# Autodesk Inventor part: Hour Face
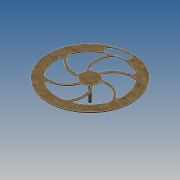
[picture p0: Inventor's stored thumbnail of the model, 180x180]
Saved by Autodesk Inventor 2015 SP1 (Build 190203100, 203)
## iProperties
Created: 2015-01
Part Number: Hour Face
Material: Generic
Document SubType Name: Modeling
Designer: Steve Brooks
Density: 1 g/cm^3
Appearance: IDS MDF
Author: Steve Brooks
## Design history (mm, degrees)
sketch "Sketch1"
  geometry: C1 r 3 at (-234.295, -144.93) reference; C2 r 6.747 at (-234.295, -144.93) reference; 1 further point
extrude "Extrusion1" new body sketch "Sketch1" distance "d0" = 108; taper "d1" = 0 deg
sketch "Sketch2"
  geometry: L1 (200.947, -79.304)-(203.637, -72.118) reference; C1 r 6.747 at (0, 0) reference; C2 r 3 at (0, 0) reference; C3 r 225 at (0, 0); 1 further point
  constraints: 1 centre point, 1 coincident
  dimensions: "d9" = 450 diameter of C3
extrude "Extrusion2" new body sketch "Sketch2" distance "d3" = 6; taper "d4" = 0 deg
sketch "Sketch3"
  geometry: L1 (0, 0)-(0, 198); L2 (0, 0)-(-77.365, 182.26); C1 r 3 at (0, 0) reference; C2 r 6.747 at (0, 0) reference; A1 r 20 centre (0, 198) between (0, 178) and (0, 218); A2 r 20 centre (-77.365, 182.26) between (-85.179, 200.67) and (-69.55, 163.85); A3 r 178 centre (0, 0) between (0, 178) and (-69.55, 163.85); A4 r 218 centre (0, 0) between (0, 218) and (-85.179, 200.67); 1 further point
  constraints: 8 point on circle, 4 centre point, 4 end point, 3 tangent, 2 coincident, 1 vertical
  dimensions: "d5" = 40 diameter of A1; "d6" = 198 distance of L1.end point (0, 0); "d21" = 40 diameter of A2; "d22" = 23 deg angle of L1 L2
sketch "Sketch4"
  geometry: C1 r 6.747 at (0, 0) reference; C2 r 3 at (0, 0) reference; A1 r 106.588 centre (45, 100.374) between (-36.681, 168.853) and (-41.383, 37.931); A2 r 116.588 centre (45, 100.374) between (-62.871, 144.608) and (-44.081, 25.158); A3 r 106.588 centre (-64.427, 89.158) between (-164.571, 52.66) and (-53.541, -16.873); A4 r 116.588 centre (-64.427, 89.158) between (-156.67, 17.856) and (-43.828, -25.596); A5 r 106.588 centre (-109.427, -11.216) between (-127.89, -116.193) and (-12.158, -54.804); A6 r 116.588 centre (-109.427, -11.216) between (-93.798, -126.752) and (0.253, -50.754); A7 r 106.588 centre (-45, -100.374) between (36.681, -168.853) and (41.383, -37.931); A8 r 116.588 centre (-45, -100.374) between (62.871, -144.608) and (44.081, -25.158); A9 r 106.588 centre (64.427, -89.158) between (164.571, -52.66) and (53.541, 16.873); A10 r 116.588 centre (64.427, -89.158) between (156.67, -17.856) and (43.828, 25.596); A11 r 106.588 centre (109.427, 11.216) between (131.472, 115.5) and (12.158, 54.804); A12 r 116.588 centre (109.427, 11.216) between (93.798, 126.752) and (-0.253, 50.754); A13 r 175 centre (0, 0) between (-76.495, 157.396) and (-164.581, 59.483); A14 r 175 centre (0, 0) between (98.062, 144.945) and (-30.776, 172.272); A15 r 175 centre (0, 0) between (174.556, -12.451) and (131.472, 115.5); A16 r 175 centre (0, 0) between (76.495, -157.396) and (164.581, -59.483); A17 r 175 centre (0, 0) between (-174.556, 12.451) and (-133.804, -112.789); A18 r 175 centre (0, 0) between (-98.062, -144.945) and (30.776, -172.272); A19 r 45 centre (0, 0) between (-42.317, 15.305) and (-44.642, -5.666); A20 r 45 centre (0, 0) between (42.317, -15.305) and (44.642, 5.666); A21 r 45 centre (0, 0) between (-34.413, -28.995) and (-17.414, -41.494); A22 r 45 centre (0, 0) between (7.904, -44.3) and (27.228, -35.828); A23 r 10 centre (-72.124, 148.402) between (-62.871, 144.608) and (-76.495, 157.396); A24 r 10 centre (92.458, 136.662) between (93.798, 126.752) and (98.062, 144.945); A25 r 10 centre (164.582, -11.74) between (156.67, -17.856) and (174.556, -12.451); A26 r 10 centre (72.124, -148.402) between (62.871, -144.608) and (76.495, -157.396); A27 r 10 centre (-92.458, -136.662) between (-93.798, -126.752) and (-98.062, -144.945); A28 r 10 centre (-164.582, 11.74) between (-156.67, 17.856) and (-174.556, 12.451); A29 r 10 centre (-155.176, 56.084) between (-164.581, 59.483) and (-164.571, 52.66); A30 r 10 centre (29.018, -162.428) between (30.776, -172.272) and (36.681, -168.853); A31 r 10 centre (-51.721, 18.706) between (-42.317, 15.305) and (-44.081, 25.158); A32 r 10 centre (-54.562, -6.925) between (-53.541, -16.873) and (-44.642, -5.666); A33 r 10 centre (-42.061, -35.439) between (-34.413, -28.995) and (-43.828, -25.596); A34 r 10 centre (-21.284, -50.715) between (-12.158, -54.804) and (-17.414, -41.494); A35 r 10 centre (-126.158, -106.344) between (-133.804, -112.789) and (-127.89, -116.193); A36 r 10 centre (33.278, -43.79) between (41.383, -37.931) and (27.228, -35.828); A37 r 10 centre (54.562, 6.925) between (53.541, 16.873) and (44.642, 5.666); A38 r 10 centre (42.061, 35.439) between (34.413, 28.995) and (43.828, 25.596); A39 r 45 centre (0, 0) between (34.413, 28.995) and (17.414, 41.494); A40 r 45 centre (0, 0) between (-7.904, 44.3) and (-27.228, 35.828); A41 r 10 centre (-33.278, 43.79) between (-41.383, 37.931) and (-27.228, 35.828); A42 r 10 centre (-9.66, 54.145) between (-7.904, 44.3) and (-0.253, 50.754); A43 r 10 centre (21.284, 50.715) between (12.158, 54.804) and (17.414, 41.494); A44 r 10 centre (51.721, -18.706) between (42.317, -15.305) and (44.081, -25.158); A45 r 10 centre (9.66, -54.145) between (7.904, -44.3) and (0.253, -50.754); A46 r 10 centre (155.176, -56.084) between (164.581, -59.483) and (164.571, -52.66); A47 r 10 centre (-29.018, 162.428) between (-30.776, 172.272) and (-36.681, 168.853); 2 further points
  constraints: 94 point on circle, 47 centre point, 45 tangent, 20 equal radius, 3 coincident, 3 other
  dimensions: "d12" = 10 radial gap between concentric circles of A1 A2; "d16" = 10 radius of A23; "d17" = 10 radius of A34; "d18" = 10 radius of A41
extrude "Extrusion5" cut sketch "Sketch3" stored distance "d23" = 10; taper "d24" = 0 deg
extrude "Extrusion6" cut sketch "Sketch4" stored distance "d25" = 10; taper "d26" = 0 deg
body "Solid1"
node "Reference1"
node "Reference2"
node "Reference3"
body "Solid2"
